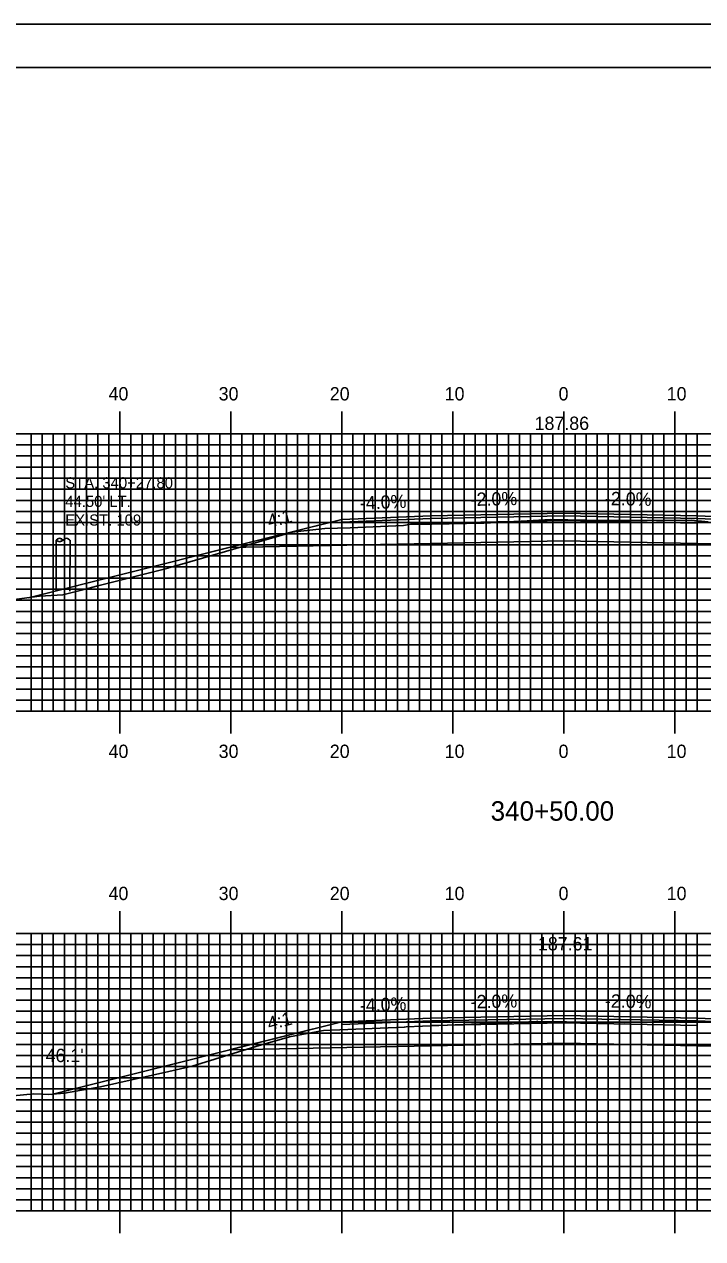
# Model space of a CAD drawing. Extents: x 1824360 to 1824703, y 442591 to 442811.
# Drawn here: x 1824476.7 to 1824537.8, y 442701.2 to 442810.5 of the extents above; entities that cross this region are included whole.
import ezdxf

# ---------------------------------------------------------------- set-up
doc = ezdxf.new("R2010")
doc.units = 0
for name, color, linetype in [('ANNOTATION', 7, 'Continuous'), ('BORDER', 7, 'Continuous'), ('D_Roadway_Centerline', 7, 'Continuous'), ('D_Roadway_Centerline_Text', 7, 'Continuous'), ('D_Roadway_Edge_Shoulder', 7, 'Continuous'), ('D_Roadway_Edge_TW', 7, 'Continuous'), ('D_Roadway_Pavement', 7, 'Continuous'), ('D_Roadway_SlopeLines', 7, 'Continuous'), ('D_Roadway_SubGrade', 7, 'Continuous'), ('D_Text_Monospaced', 7, 'Continuous'), ('D_Text_Standard', 7, 'Continuous'), ('H_V ANNOTATION', 7, 'Continuous'), ('MAJOR', 7, 'Continuous'), ('MINOR', 7, 'Continuous'), ('PLOT BOUNDARY', 7, 'Continuous'), ('S_Roadway_Centerline', 7, 'Continuous'), ('S_Utilities_Pole_Power', 7, 'Continuous')]:
    doc.layers.add(name, color=color, linetype=linetype)

msp = doc.modelspace()

# ---------------------------------------------------------------- linework, layer by layer
at = {"layer": 'BORDER'}
msp.add_lwpolyline([(1824375.73, 442596.67), (1824695.73, 442596.67), (1824695.73, 442806.67), (1824375.73, 442806.67)], close=True, dxfattribs=at)
at = {"layer": 'D_Roadway_Centerline'}
msp.add_lwpolyline([(1824477.1, 442758.9), (1824495.16, 442763.42), (1824505.33, 442765.96), (1824513.33, 442766.28), (1824525.33, 442766.52), (1824537.33, 442766.28), (1824545.33, 442765.96), (1824555.51, 442763.42), (1824570.07, 442759.78)], dxfattribs=at)
at = {"layer": 'D_Roadway_Edge_Shoulder'}
for points in [[(1824513.33, 442766.28), (1824505.33, 442765.96), (1824505.33, 442765.71), (1824513.33, 442766.03)], [(1824537.33, 442766.28), (1824545.33, 442765.96), (1824545.33, 442765.71), (1824537.33, 442766.03)], [(1824513.33, 442721.03), (1824505.33, 442720.71), (1824505.33, 442720.46), (1824513.33, 442720.78)], [(1824537.33, 442721.03), (1824545.33, 442720.71), (1824545.33, 442720.46), (1824537.33, 442720.78)]]:
    msp.add_lwpolyline(points, close=True, dxfattribs=at)
at = {"layer": 'D_Roadway_Edge_TW'}
for points in [[(1824513.33, 442766.03), (1824513.33, 442766.28), (1824525.33, 442766.52), (1824537.33, 442766.28), (1824537.33, 442766.03), (1824525.33, 442766.27)], [(1824513.33, 442720.78), (1824513.33, 442721.03), (1824525.33, 442721.27), (1824537.33, 442721.03), (1824537.33, 442720.78), (1824525.33, 442721.02)]]:
    msp.add_lwpolyline(points, close=True, dxfattribs=at)
at = {"layer": 'D_Roadway_Pavement'}
for points in [[(1824513.33, 442765.62), (1824513.33, 442766.03), (1824525.33, 442766.27), (1824537.33, 442766.03), (1824537.33, 442765.62), (1824525.33, 442765.86)], [(1824513.33, 442720.37), (1824513.33, 442720.78), (1824525.33, 442721.02), (1824537.33, 442720.78), (1824537.33, 442720.37), (1824525.33, 442720.61)]]:
    msp.add_lwpolyline(points, close=True, dxfattribs=at)
at = {"layer": 'D_Roadway_SlopeLines'}
for points in [[(1824505.33, 442765.96), (1824493.33, 442762.96)], [(1824505.33, 442720.71), (1824479.18, 442714.17)]]:
    msp.add_lwpolyline(points, dxfattribs=at)
at = {"layer": 'D_Roadway_SubGrade'}
for points in [[(1824513.33, 442763.78), (1824495.16, 442763.42), (1824505.33, 442765.96), (1824505.33, 442765.71), (1824513.33, 442766.03), (1824525.33, 442766.27), (1824537.33, 442766.03), (1824545.33, 442765.71), (1824545.33, 442765.96), (1824555.51, 442763.42), (1824537.33, 442763.78), (1824525.33, 442764.02)], [(1824513.33, 442718.53), (1824495.16, 442718.17), (1824505.33, 442720.71), (1824505.33, 442720.46), (1824513.33, 442720.78), (1824525.33, 442721.02), (1824537.33, 442720.78), (1824545.33, 442720.46), (1824545.33, 442720.71), (1824555.51, 442718.17), (1824537.33, 442718.53), (1824525.33, 442718.77)]]:
    msp.add_lwpolyline(points, close=True, dxfattribs=at)
at = {"layer": 'MAJOR'}
for p, q in [((1824485.33, 442775.67), (1824485.33, 442773.67)), ((1824495.33, 442775.67), (1824495.33, 442773.67)), ((1824505.33, 442775.67), (1824505.33, 442773.67)), ((1824515.33, 442775.67), (1824515.33, 442773.67)), ((1824525.33, 442775.67), (1824525.33, 442773.67)), ((1824535.33, 442775.67), (1824535.33, 442773.67)), ((1824385.33, 442773.67), (1824665.33, 442773.67)), ((1824385.33, 442773.67), (1824665.33, 442773.67)), ((1824485.33, 442748.67), (1824485.33, 442773.67)), ((1824495.33, 442748.67), (1824495.33, 442773.67)), ((1824505.33, 442748.67), (1824505.33, 442773.67)), ((1824515.33, 442748.67), (1824515.33, 442773.67)), ((1824525.33, 442748.67), (1824525.33, 442773.67)), ((1824535.33, 442748.67), (1824535.33, 442773.67)), ((1824385.33, 442768.67), (1824665.33, 442768.67)), ((1824385.33, 442763.67), (1824665.33, 442763.67)), ((1824385.33, 442758.67), (1824665.33, 442758.67)), ((1824385.33, 442753.67), (1824665.33, 442753.67)), ((1824385.33, 442748.67), (1824665.33, 442748.67)), ((1824385.33, 442748.67), (1824665.33, 442748.67)), ((1824485.33, 442746.66), (1824485.33, 442748.67)), ((1824495.33, 442746.66), (1824495.33, 442748.67)), ((1824505.33, 442746.66), (1824505.33, 442748.67)), ((1824515.33, 442746.66), (1824515.33, 442748.67)), ((1824525.33, 442746.66), (1824525.33, 442748.67)), ((1824535.33, 442746.66), (1824535.33, 442748.67)), ((1824485.33, 442730.67), (1824485.33, 442728.67)), ((1824495.33, 442730.67), (1824495.33, 442728.67)), ((1824505.33, 442730.67), (1824505.33, 442728.67)), ((1824515.33, 442730.67), (1824515.33, 442728.67)), ((1824525.33, 442730.67), (1824525.33, 442728.67)), ((1824535.33, 442730.67), (1824535.33, 442728.67)), ((1824385.33, 442728.67), (1824665.33, 442728.67)), ((1824385.33, 442728.67), (1824665.33, 442728.67)), ((1824485.33, 442703.67), (1824485.33, 442728.67)), ((1824495.33, 442703.67), (1824495.33, 442728.67)), ((1824505.33, 442703.67), (1824505.33, 442728.67)), ((1824515.33, 442703.67), (1824515.33, 442728.67)), ((1824525.33, 442703.67), (1824525.33, 442728.67)), ((1824535.33, 442703.67), (1824535.33, 442728.67)), ((1824385.33, 442723.67), (1824665.33, 442723.67)), ((1824385.33, 442718.67), (1824665.33, 442718.67)), ((1824385.33, 442713.67), (1824665.33, 442713.67)), ((1824385.33, 442708.67), (1824665.33, 442708.67)), ((1824385.33, 442703.67), (1824665.33, 442703.67)), ((1824385.33, 442703.67), (1824665.33, 442703.67)), ((1824485.33, 442701.66), (1824485.33, 442703.67)), ((1824495.33, 442701.66), (1824495.33, 442703.67)), ((1824505.33, 442701.66), (1824505.33, 442703.67)), ((1824515.33, 442701.66), (1824515.33, 442703.67)), ((1824525.33, 442701.66), (1824525.33, 442703.67)), ((1824535.33, 442701.66), (1824535.33, 442703.67))]:
    msp.add_line(p, q, dxfattribs=at)
at = {"layer": 'MINOR'}
for p, q in [((1824477.33, 442748.67), (1824477.33, 442773.67)), ((1824478.33, 442748.67), (1824478.33, 442773.67)), ((1824479.33, 442748.67), (1824479.33, 442773.67)), ((1824480.33, 442748.67), (1824480.33, 442773.67)), ((1824481.33, 442748.67), (1824481.33, 442773.67)), ((1824482.33, 442748.67), (1824482.33, 442773.67)), ((1824483.33, 442748.67), (1824483.33, 442773.67)), ((1824484.33, 442748.67), (1824484.33, 442773.67)), ((1824486.33, 442748.67), (1824486.33, 442773.67)), ((1824487.33, 442748.67), (1824487.33, 442773.67)), ((1824488.33, 442748.67), (1824488.33, 442773.67)), ((1824489.33, 442748.67), (1824489.33, 442773.67)), ((1824490.33, 442748.67), (1824490.33, 442773.67)), ((1824491.33, 442748.67), (1824491.33, 442773.67)), ((1824492.33, 442748.67), (1824492.33, 442773.67)), ((1824493.33, 442748.67), (1824493.33, 442773.67)), ((1824494.33, 442748.67), (1824494.33, 442773.67)), ((1824496.33, 442748.67), (1824496.33, 442773.67)), ((1824497.33, 442748.67), (1824497.33, 442773.67)), ((1824498.33, 442748.67), (1824498.33, 442773.67)), ((1824499.33, 442748.67), (1824499.33, 442773.67)), ((1824500.33, 442748.67), (1824500.33, 442773.67)), ((1824501.33, 442748.67), (1824501.33, 442773.67)), ((1824502.33, 442748.67), (1824502.33, 442773.67)), ((1824503.33, 442748.67), (1824503.33, 442773.67)), ((1824504.33, 442748.67), (1824504.33, 442773.67)), ((1824506.33, 442748.67), (1824506.33, 442773.67)), ((1824507.33, 442748.67), (1824507.33, 442773.67)), ((1824508.33, 442748.67), (1824508.33, 442773.67)), ((1824509.33, 442748.67), (1824509.33, 442773.67)), ((1824510.33, 442748.67), (1824510.33, 442773.67)), ((1824511.33, 442748.67), (1824511.33, 442773.67)), ((1824512.33, 442748.67), (1824512.33, 442773.67)), ((1824513.33, 442748.67), (1824513.33, 442773.67)), ((1824514.33, 442748.67), (1824514.33, 442773.67)), ((1824516.33, 442748.67), (1824516.33, 442773.67)), ((1824517.33, 442748.67), (1824517.33, 442773.67)), ((1824518.33, 442748.67), (1824518.33, 442773.67)), ((1824519.33, 442748.67), (1824519.33, 442773.67)), ((1824520.33, 442748.67), (1824520.33, 442773.67)), ((1824521.33, 442748.67), (1824521.33, 442773.67)), ((1824522.33, 442748.67), (1824522.33, 442773.67)), ((1824523.33, 442748.67), (1824523.33, 442773.67)), ((1824524.33, 442748.67), (1824524.33, 442773.67)), ((1824526.33, 442748.67), (1824526.33, 442773.67)), ((1824527.33, 442748.67), (1824527.33, 442773.67)), ((1824528.33, 442748.67), (1824528.33, 442773.67)), ((1824529.33, 442748.67), (1824529.33, 442773.67)), ((1824530.33, 442748.67), (1824530.33, 442773.67)), ((1824531.33, 442748.67), (1824531.33, 442773.67)), ((1824532.33, 442748.67), (1824532.33, 442773.67)), ((1824533.33, 442748.67), (1824533.33, 442773.67)), ((1824534.33, 442748.67), (1824534.33, 442773.67)), ((1824536.33, 442748.67), (1824536.33, 442773.67)), ((1824537.33, 442748.67), (1824537.33, 442773.67)), ((1824385.33, 442772.67), (1824665.33, 442772.67)), ((1824385.33, 442771.67), (1824665.33, 442771.67)), ((1824385.33, 442770.67), (1824665.33, 442770.67)), ((1824385.33, 442769.67), (1824665.33, 442769.67)), ((1824385.33, 442767.67), (1824665.33, 442767.67)), ((1824385.33, 442766.67), (1824665.33, 442766.67)), ((1824385.33, 442765.67), (1824665.33, 442765.67)), ((1824385.33, 442764.67), (1824665.33, 442764.67)), ((1824385.33, 442762.67), (1824665.33, 442762.67)), ((1824385.33, 442761.67), (1824665.33, 442761.67)), ((1824385.33, 442760.67), (1824665.33, 442760.67)), ((1824385.33, 442759.67), (1824665.33, 442759.67)), ((1824385.33, 442757.67), (1824665.33, 442757.67)), ((1824385.33, 442756.67), (1824665.33, 442756.67)), ((1824385.33, 442755.67), (1824665.33, 442755.67)), ((1824385.33, 442754.67), (1824665.33, 442754.67)), ((1824385.33, 442752.67), (1824665.33, 442752.67)), ((1824385.33, 442751.67), (1824665.33, 442751.67)), ((1824385.33, 442750.67), (1824665.33, 442750.67)), ((1824385.33, 442749.67), (1824665.33, 442749.67)), ((1824477.33, 442703.67), (1824477.33, 442728.67)), ((1824478.33, 442703.67), (1824478.33, 442728.67)), ((1824479.33, 442703.67), (1824479.33, 442728.67)), ((1824480.33, 442703.67), (1824480.33, 442728.67)), ((1824481.33, 442703.67), (1824481.33, 442728.67)), ((1824482.33, 442703.67), (1824482.33, 442728.67)), ((1824483.33, 442703.67), (1824483.33, 442728.67)), ((1824484.33, 442703.67), (1824484.33, 442728.67)), ((1824486.33, 442703.67), (1824486.33, 442728.67)), ((1824487.33, 442703.67), (1824487.33, 442728.67)), ((1824488.33, 442703.67), (1824488.33, 442728.67)), ((1824489.33, 442703.67), (1824489.33, 442728.67)), ((1824490.33, 442703.67), (1824490.33, 442728.67)), ((1824491.33, 442703.67), (1824491.33, 442728.67)), ((1824492.33, 442703.67), (1824492.33, 442728.67)), ((1824493.33, 442703.67), (1824493.33, 442728.67)), ((1824494.33, 442703.67), (1824494.33, 442728.67)), ((1824496.33, 442703.67), (1824496.33, 442728.67)), ((1824497.33, 442703.67), (1824497.33, 442728.67)), ((1824498.33, 442703.67), (1824498.33, 442728.67)), ((1824499.33, 442703.67), (1824499.33, 442728.67)), ((1824500.33, 442703.67), (1824500.33, 442728.67)), ((1824501.33, 442703.67), (1824501.33, 442728.67)), ((1824502.33, 442703.67), (1824502.33, 442728.67)), ((1824503.33, 442703.67), (1824503.33, 442728.67)), ((1824504.33, 442703.67), (1824504.33, 442728.67)), ((1824506.33, 442703.67), (1824506.33, 442728.67)), ((1824507.33, 442703.67), (1824507.33, 442728.67)), ((1824508.33, 442703.67), (1824508.33, 442728.67)), ((1824509.33, 442703.67), (1824509.33, 442728.67)), ((1824510.33, 442703.67), (1824510.33, 442728.67)), ((1824511.33, 442703.67), (1824511.33, 442728.67)), ((1824512.33, 442703.67), (1824512.33, 442728.67)), ((1824513.33, 442703.67), (1824513.33, 442728.67)), ((1824514.33, 442703.67), (1824514.33, 442728.67)), ((1824516.33, 442703.67), (1824516.33, 442728.67)), ((1824517.33, 442703.67), (1824517.33, 442728.67)), ((1824518.33, 442703.67), (1824518.33, 442728.67)), ((1824519.33, 442703.67), (1824519.33, 442728.67)), ((1824520.33, 442703.67), (1824520.33, 442728.67)), ((1824521.33, 442703.67), (1824521.33, 442728.67)), ((1824522.33, 442703.67), (1824522.33, 442728.67)), ((1824523.33, 442703.67), (1824523.33, 442728.67)), ((1824524.33, 442703.67), (1824524.33, 442728.67)), ((1824526.33, 442703.67), (1824526.33, 442728.67)), ((1824527.33, 442703.67), (1824527.33, 442728.67)), ((1824528.33, 442703.67), (1824528.33, 442728.67)), ((1824529.33, 442703.67), (1824529.33, 442728.67)), ((1824530.33, 442703.67), (1824530.33, 442728.67)), ((1824531.33, 442703.67), (1824531.33, 442728.67)), ((1824532.33, 442703.67), (1824532.33, 442728.67)), ((1824533.33, 442703.67), (1824533.33, 442728.67)), ((1824534.33, 442703.67), (1824534.33, 442728.67)), ((1824536.33, 442703.67), (1824536.33, 442728.67)), ((1824537.33, 442703.67), (1824537.33, 442728.67)), ((1824385.33, 442727.67), (1824665.33, 442727.67)), ((1824385.33, 442726.67), (1824665.33, 442726.67)), ((1824385.33, 442725.67), (1824665.33, 442725.67)), ((1824385.33, 442724.67), (1824665.33, 442724.67)), ((1824385.33, 442722.67), (1824665.33, 442722.67)), ((1824385.33, 442721.67), (1824665.33, 442721.67)), ((1824385.33, 442720.67), (1824665.33, 442720.67)), ((1824385.33, 442719.67), (1824665.33, 442719.67)), ((1824385.33, 442717.67), (1824665.33, 442717.67)), ((1824385.33, 442716.67), (1824665.33, 442716.67)), ((1824385.33, 442715.67), (1824665.33, 442715.67)), ((1824385.33, 442714.67), (1824665.33, 442714.67)), ((1824385.33, 442712.67), (1824665.33, 442712.67)), ((1824385.33, 442711.67), (1824665.33, 442711.67)), ((1824385.33, 442710.67), (1824665.33, 442710.67)), ((1824385.33, 442709.67), (1824665.33, 442709.67)), ((1824385.33, 442707.67), (1824665.33, 442707.67)), ((1824385.33, 442706.67), (1824665.33, 442706.67)), ((1824385.33, 442705.67), (1824665.33, 442705.67)), ((1824385.33, 442704.67), (1824665.33, 442704.67))]:
    msp.add_line(p, q, dxfattribs=at)
at = {"layer": 'PLOT BOUNDARY'}
msp.add_lwpolyline([(1824359.55, 442590.55), (1824699.55, 442590.55), (1824699.55, 442810.55), (1824359.55, 442810.55)], close=True, dxfattribs=at)
at = {"layer": 'S_Roadway_Centerline'}
for points in [[(1824470.83, 442758.09), (1824478.1, 442759.03), (1824479.69, 442759.14), (1824480.19, 442759.15), (1824482.24, 442759.68), (1824483.23, 442759.95), (1824489.69, 442761.57), (1824489.71, 442761.58), (1824489.71, 442761.58), (1824490.69, 442761.86), (1824500.86, 442764.81), (1824501.04, 442764.85), (1824501.09, 442764.85), (1824503.79, 442765.14), (1824506.08, 442765.21), (1824510.88, 442765.42), (1824511.38, 442765.5), (1824511.54, 442765.54), (1824513.44, 442765.52), (1824518.13, 442765.62), (1824519.34, 442765.67), (1824524.15, 442765.94), (1824527.24, 442765.89), (1824533.66, 442765.86), (1824534.35, 442765.87), (1824534.37, 442765.86), (1824536.78, 442765.9), (1824538.33, 442765.75)], [(1824471.62, 442713.65), (1824477.58, 442714.21), (1824478.92, 442714.15), (1824480.35, 442714.27), (1824483.57, 442714.84), (1824489.75, 442716.24), (1824491.84, 442716.71), (1824497.59, 442718.47), (1824500.62, 442719.36), (1824501.72, 442719.57), (1824503.5, 442719.9), (1824503.68, 442719.93), (1824510.96, 442720.23), (1824510.96, 442720.23), (1824510.96, 442720.23), (1824511.11, 442720.24), (1824522.88, 442720.74), (1824522.89, 442720.75), (1824522.95, 442720.74), (1824530.8, 442720.64), (1824535.92, 442720.76), (1824536.02, 442720.76), (1824536.07, 442720.75), (1824543.24, 442720.49)]]:
    msp.add_lwpolyline(points, dxfattribs=at)
at = {"layer": 'S_Utilities_Pole_Power'}
for p, q in [((1824479.58, 442764.1), (1824479.74, 442764.21)), ((1824479.58, 442759.48), (1824479.59, 442764.1)), ((1824479.74, 442763.99), (1824479.58, 442764.1)), ((1824480.05, 442764.21), (1824480.21, 442764.1)), ((1824480.21, 442764.1), (1824480.05, 442763.99)), ((1824480.37, 442764.21), (1824480.21, 442764.1)), ((1824480.83, 442764.1), (1824480.68, 442764.21)), ((1824480.83, 442759.48), (1824480.84, 442764.1))]:
    msp.add_line(p, q, dxfattribs=at)
for centre, start, end in [((1824479.9, 442763.99), 90, 125.2644), ((1824479.9, 442764.21), 234.7356, 270), ((1824479.9, 442763.99), 54.7356, 90), ((1824479.9, 442764.21), 270, 305.2644), ((1824480.52, 442763.99), 90, 125.2644), ((1824480.52, 442763.99), 54.7356, 90)]:
    msp.add_arc(centre, 0.271, start, end, dxfattribs=at)

# ---------------------------------------------------------------- texts
at = {"layer": 'ANNOTATION'}
for s, rotation, p in [('-4.0%', 2.2906, (1824506.97, 442766.83)), ('-2.0%', 1.1458, (1824516.94, 442767.16)), ('-2.0%', 358.8542, (1824529.02, 442767.25)), ('4:1', 14.0362, (1824498.78, 442765.19)), ('-4.0%', 2.2906, (1824506.97, 442721.58)), ('-2.0%', 1.1458, (1824516.94, 442721.91)), ('-2.0%', 358.8542, (1824529.02, 442722)), ('4:1', 14.0362, (1824498.78, 442719.94))]:
    msp.add_text(s, height=1.2, rotation=rotation, dxfattribs=at).set_placement(p)
at = {"layer": 'D_Roadway_Centerline'}
for s, p in [('C', (1824525.33, 442766.52)), ('L', (1824525.33, 442766.52)), ('C', (1824525.33, 442721.27)), ('L', (1824525.33, 442721.27))]:
    msp.add_text(s, height=0.0146, dxfattribs=at).set_placement(p)
at = {"layer": 'D_Roadway_Centerline_Text'}
for s, p in [('187.86', (1824522.69, 442774.01)), ('187.61', (1824522.99, 442727.14))]:
    msp.add_text(s, height=1.2, dxfattribs=at).set_placement(p)
at = {"layer": 'D_Text_Monospaced'}
for s, p in [('STA. 340+27.80', (1824480.41, 442768.75)), ("44.50' LT.", (1824480.41, 442767.08)), ('EXIST. 109', (1824480.41, 442765.4))]:
    msp.add_text(s, height=1, dxfattribs=at).set_placement(p)
at = {"layer": 'D_Text_Standard'}
msp.add_text("46.1'", height=1.2, dxfattribs=at).set_placement((1824478.64, 442717.08))
at = {"layer": 'H_V ANNOTATION'}
for s, height, p in [('40', 1.2, (1824484.31, 442776.67)), ('30', 1.2, (1824494.23, 442776.67)), ('20', 1.2, (1824504.24, 442776.67)), ('10', 1.2, (1824514.59, 442776.67)), ('0', 1.2, (1824524.85, 442776.67)), ('10', 1.2, (1824534.59, 442776.67)), ('40', 1.2, (1824484.31, 442744.47)), ('30', 1.2, (1824494.23, 442744.47)), ('20', 1.2, (1824504.24, 442744.47)), ('10', 1.2, (1824514.59, 442744.47)), ('0', 1.2, (1824524.85, 442744.47)), ('10', 1.2, (1824534.59, 442744.47)), ('340+50.00', 1.75, (1824518.73, 442738.82)), ('40', 1.2, (1824484.31, 442731.67)), ('30', 1.2, (1824494.23, 442731.67)), ('20', 1.2, (1824504.24, 442731.67)), ('10', 1.2, (1824514.59, 442731.67)), ('0', 1.2, (1824524.85, 442731.67)), ('10', 1.2, (1824534.59, 442731.67))]:
    msp.add_text(s, height=height, dxfattribs=at).set_placement(p)
at = {"layer": 'S_Roadway_Centerline'}
for s, p in [('L', (1824524.14, 442765.93)), ('C', (1824524.14, 442765.94)), ('C', (1824522.88, 442720.75)), ('L', (1824522.88, 442720.74))]:
    msp.add_text(s, height=0.0146, dxfattribs=at).set_placement(p)

doc.saveas('drawing.dxf')
